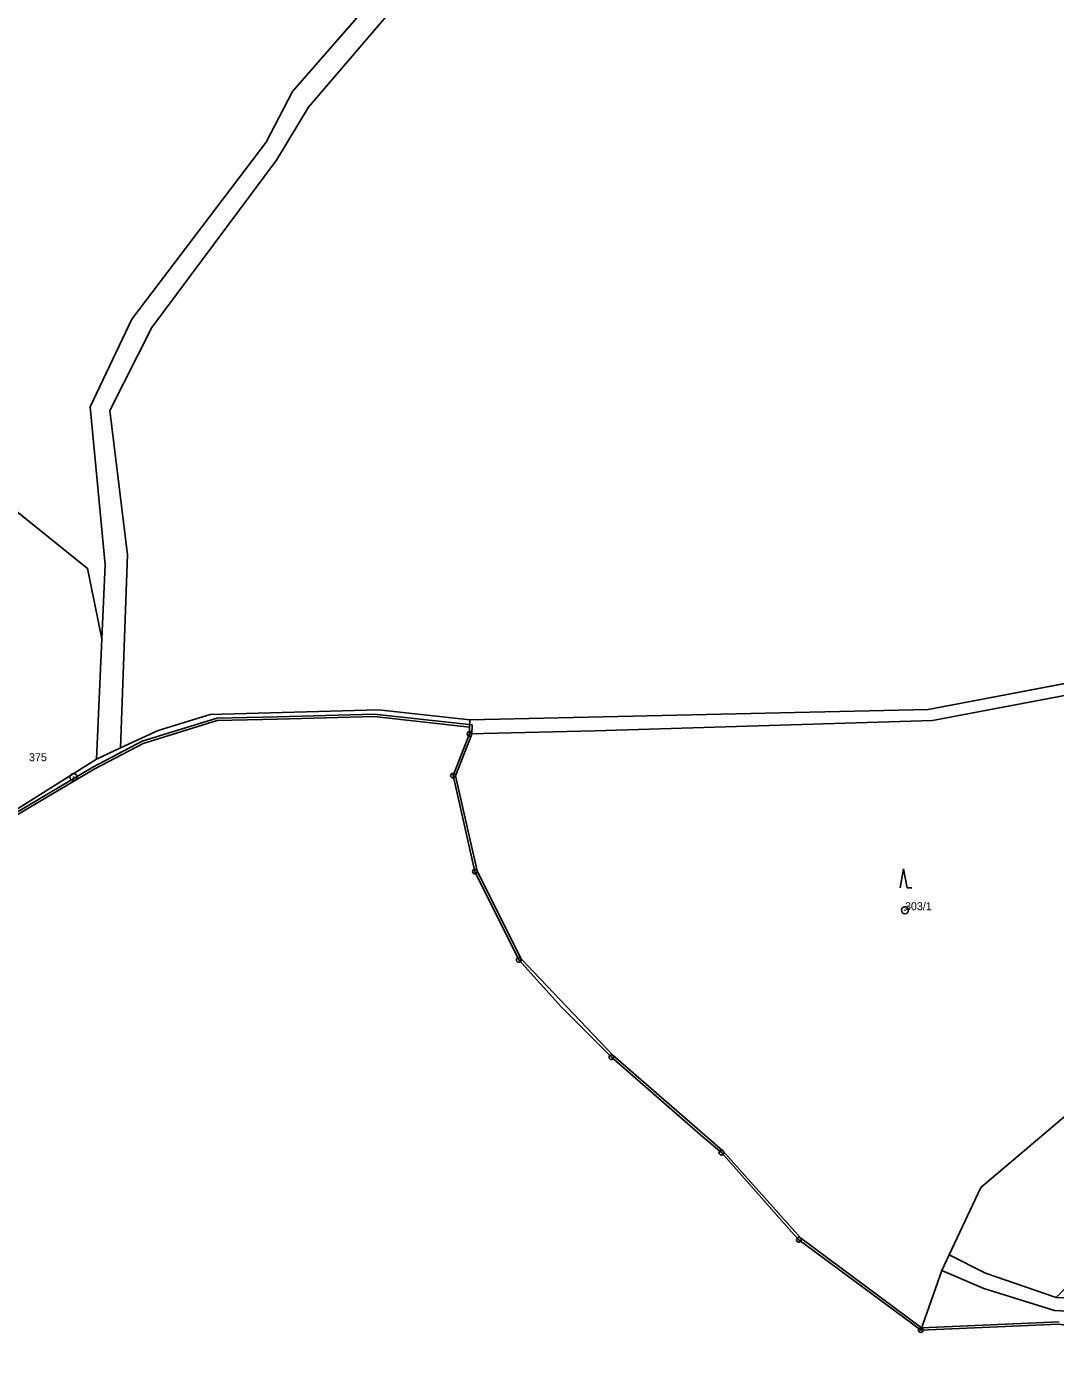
# Model space of a CAD drawing. Extents: x -652854 to -650068, y -1097661 to -1095417.
# Drawn here: x -651919.6 to -651701, y -1097612.7 to -1097329.6 of the extents above; entities that cross this region are included whole.
import ezdxf

# ---------------------------------------------------------------- set-up
doc = ezdxf.new("R2010")
doc.units = 0
for name, color, linetype in [('Definiční body parcel', 7, 'Continuous'), ('Geodetické body', 7, 'Continuous'), ('Hranice obcí', 7, 'Continuous'), ('Hranice parcel', 7, 'Continuous'), ('Obvody jako plochy', 7, 'Continuous'), ('Ostatní hranice', 7, 'Continuous'), ('Parcelní čísla', 7, 'Continuous'), ('Prvky pro prodl_ par_ č_', 7, 'Continuous'), ('Značky kultur', 7, 'Continuous')]:
    doc.layers.add(name, color=color, linetype=linetype)

msp = doc.modelspace()

# ---------------------------------------------------------------- linework, layer by layer
at = {"layer": 'Definiční body parcel'}
for centre, radius in [((-651909.62, -1097489), 0.75), ((-651909.62, -1097489), 0.0327), ((-651732.94, -1097517.28), 0.75), ((-651732.94, -1097517.28), 0.0327)]:
    msp.add_circle(centre, radius, dxfattribs=at)
at = {"layer": 'Geodetické body'}
for centre, radius in [((-651825.47, -1097479.81), 0.5), ((-651825.47, -1097479.81), 0.001), ((-651828.98, -1097488.69), 0.5), ((-651828.98, -1097488.69), 0.001), ((-651824.33, -1097509.08), 0.5), ((-651824.33, -1097509.08), 0.001), ((-651815, -1097527.82), 0.5), ((-651815, -1097527.82), 0.001), ((-651795.32, -1097548.52), 0.5), ((-651795.32, -1097548.52), 0.001), ((-651771.96, -1097568.78), 0.5), ((-651771.96, -1097568.78), 0.001), ((-651755.48, -1097587.3), 0.5), ((-651755.48, -1097587.3), 0.001), ((-651729.58, -1097606.47), 0.5), ((-651729.58, -1097606.47), 0.5), ((-651729.58, -1097606.47), 0.001), ((-651729.58, -1097606.47), 0.001)]:
    msp.add_circle(centre, radius, dxfattribs=at)
at = {"layer": 'Hranice obcí'}
for p, q in [((-651845.76, -1097476.13), (-651866.27, -1097476.71)), ((-651825.44, -1097478.37), (-651845.76, -1097476.13)), ((-651879.09, -1097476.97), (-651894.83, -1097481.83)), ((-651866.27, -1097476.71), (-651879.09, -1097476.97)), ((-651825.47, -1097479.81), (-651825.44, -1097478.37)), ((-651894.83, -1097481.83), (-651905.26, -1097487.34)), ((-651828.98, -1097488.69), (-651825.47, -1097479.81)), ((-651905.26, -1097487.34), (-651927.04, -1097500.22)), ((-651824.33, -1097509.08), (-651828.98, -1097488.69)), ((-651815, -1097527.82), (-651824.33, -1097509.08)), ((-651805.95, -1097537.85), (-651815, -1097527.82)), ((-651795.32, -1097548.52), (-651805.95, -1097537.85)), ((-651795.32, -1097548.52), (-651775.8, -1097565.46)), ((-651775.8, -1097565.46), (-651771.96, -1097568.78)), ((-651771.96, -1097568.78), (-651756.45, -1097586.21)), ((-651756.45, -1097586.21), (-651755.48, -1097587.3)), ((-651755.48, -1097587.3), (-651731.57, -1097605)), ((-651731.57, -1097605), (-651729.58, -1097606.47)), ((-651700.22, -1097605.21), (-651729.58, -1097606.47))]:
    msp.add_line(p, q, dxfattribs=at)
at = {"layer": 'Hranice parcel'}
for p, q in [((-651843.88, -1097321.35), (-651863.05, -1097343.32)), ((-651840.2, -1097323.89), (-651859.69, -1097346.64)), ((-651863.05, -1097343.32), (-651868.68, -1097354.1)), ((-651859.69, -1097346.64), (-651866.47, -1097357.95)), ((-651868.68, -1097354.1), (-651897.24, -1097391.74)), ((-651866.47, -1097357.95), (-651892.98, -1097393.51)), ((-651897.24, -1097391.74), (-651906.06, -1097410.33)), ((-651892.98, -1097393.51), (-651901.87, -1097411.14)), ((-651906.06, -1097410.33), (-651902.87, -1097443.89)), ((-651901.87, -1097411.14), (-651898.12, -1097441.79)), ((-651906.62, -1097444.67), (-651926.46, -1097428.73)), ((-651898.12, -1097441.79), (-651899.65, -1097482.78)), ((-651903.58, -1097459.6), (-651906.62, -1097444.67)), ((-651902.87, -1097443.89), (-651903.58, -1097459.6)), ((-651596.98, -1097449.79), (-651728.02, -1097474.61)), ((-651727.11, -1097476.95), (-651599.33, -1097452.83)), ((-651903.58, -1097459.6), (-651904.74, -1097485.18)), ((-651880.59, -1097475.68), (-651891.62, -1097479.11)), ((-651844.81, -1097474.74), (-651880.59, -1097475.68)), ((-651825.38, -1097476.82), (-651844.81, -1097474.74)), ((-651728.02, -1097474.61), (-651825.38, -1097476.82)), ((-651891.62, -1097479.11), (-651899.65, -1097482.78)), ((-651825.47, -1097479.81), (-651798.82, -1097479.19)), ((-651825.38, -1097476.82), (-651825.44, -1097478.37)), ((-651798.82, -1097479.19), (-651727.11, -1097476.95)), ((-651899.65, -1097482.78), (-651904.74, -1097485.18)), ((-651904.74, -1097485.18), (-651928.47, -1097500.08)), ((-651686.19, -1097550.23), (-651716.83, -1097576.15)), ((-651716.83, -1097576.15), (-651723.58, -1097590.51)), ((-651723.58, -1097590.51), (-651725.08, -1097593.81)), ((-651723.58, -1097590.51), (-651715.83, -1097594.35)), ((-651725.08, -1097593.81), (-651729.58, -1097606.47)), ((-651725.08, -1097593.81), (-651716.15, -1097597.61)), ((-651715.83, -1097594.35), (-651700.83, -1097599.54)), ((-651716.15, -1097597.61), (-651701.14, -1097602.34)), ((-651701.14, -1097602.34), (-651644.13, -1097605.5))]:
    msp.add_line(p, q, dxfattribs=at)
at = {"layer": 'Obvody jako plochy'}
for points in [[(-651926.46, -1097428.73), (-651906.62, -1097444.67), (-651903.58, -1097459.6), (-651902.87, -1097443.89), (-651906.06, -1097410.33), (-651897.24, -1097391.74), (-651868.68, -1097354.1), (-651863.05, -1097343.32), (-651843.88, -1097321.35), (-651835.59, -1097289.34), (-651799.03, -1097243.39), (-651765.96, -1097199.26), (-651747.99, -1097187.53), (-651693.61, -1097158.93), (-651646.28, -1097138.78), (-651606.05, -1097138.21), (-651573.39, -1097130.09), (-651561.36, -1097123.06), (-651550.73, -1097110.1), (-651546.83, -1097095.59), (-651550.89, -1097076.68), (-651563.08, -1097040.57)], [(-651694.17, -1097165.26), (-651745.78, -1097190.99), (-651763.09, -1097202.67), (-651785, -1097232.05), (-651832.56, -1097292.73), (-651840.2, -1097323.89), (-651859.69, -1097346.64), (-651866.47, -1097357.95), (-651892.98, -1097393.51), (-651901.87, -1097411.14), (-651898.12, -1097441.79), (-651899.65, -1097482.78), (-651891.62, -1097479.11), (-651880.59, -1097475.68), (-651844.81, -1097474.74), (-651825.38, -1097476.82), (-651728.02, -1097474.61), (-651596.98, -1097449.79)], [(-651843.88, -1097321.35), (-651863.05, -1097343.32), (-651868.68, -1097354.1), (-651897.24, -1097391.74), (-651906.06, -1097410.33), (-651902.87, -1097443.89), (-651903.58, -1097459.6), (-651904.74, -1097485.18), (-651899.65, -1097482.78), (-651898.12, -1097441.79), (-651901.87, -1097411.14), (-651892.98, -1097393.51), (-651866.47, -1097357.95), (-651859.69, -1097346.64), (-651840.2, -1097323.89)], [(-651599.33, -1097452.83), (-651727.11, -1097476.95), (-651798.82, -1097479.19), (-651825.47, -1097479.81), (-651828.98, -1097488.69), (-651824.33, -1097509.08), (-651815, -1097527.82), (-651805.95, -1097537.85), (-651795.32, -1097548.52), (-651775.8, -1097565.46), (-651771.96, -1097568.78), (-651756.45, -1097586.21), (-651755.48, -1097587.3), (-651731.57, -1097605), (-651729.58, -1097606.47), (-651725.08, -1097593.81), (-651723.58, -1097590.51), (-651716.83, -1097576.15), (-651686.19, -1097550.23)]]:
    msp.add_lwpolyline(points, dxfattribs=at)
for points in [[(-651906.62, -1097444.67), (-651926.46, -1097428.73), (-651941.31, -1097422.01), (-651952.88, -1097410.23), (-651963.67, -1097405.07), (-651985.25, -1097400.69), (-652016.53, -1097380.82), (-652032.05, -1097377.13), (-652034.08, -1097388.46), (-652004.99, -1097425.22), (-651959.09, -1097482.19), (-651936.64, -1097509.95), (-651928.47, -1097500.08), (-651904.74, -1097485.18), (-651903.58, -1097459.6)], [(-651355.9, -1097395.18), (-651352.74, -1097391.59), (-651436.3, -1097432.32), (-651530.5, -1097442.54), (-651596.98, -1097449.79), (-651728.02, -1097474.61), (-651825.38, -1097476.82), (-651825.44, -1097478.37), (-651825.47, -1097479.81), (-651798.82, -1097479.19), (-651727.11, -1097476.95), (-651599.33, -1097452.83), (-651593.84, -1097451.76), (-651467.92, -1097437.92), (-651434.39, -1097434.71)], [(-651825.38, -1097476.82), (-651844.81, -1097474.74), (-651880.59, -1097475.68), (-651891.62, -1097479.11), (-651899.65, -1097482.78), (-651904.74, -1097485.18), (-651928.47, -1097500.08), (-651936.64, -1097509.95), (-651954, -1097530.05), (-651964.22, -1097538.47), (-651966.36, -1097540.92), (-651967.51, -1097542.9), (-651973.77, -1097554.49), (-651973.16, -1097555.12), (-651964.84, -1097541.04), (-651955.29, -1097533.32), (-651941.43, -1097519.36), (-651927.04, -1097500.22), (-651905.26, -1097487.34), (-651894.83, -1097481.83), (-651879.09, -1097476.97), (-651866.27, -1097476.71), (-651845.76, -1097476.13), (-651825.44, -1097478.37)], [(-651716.83, -1097576.15), (-651723.58, -1097590.51), (-651715.83, -1097594.35), (-651700.83, -1097599.54), (-651675.12, -1097574.18), (-651654.22, -1097558.94), (-651635.4, -1097533.46), (-651652.64, -1097522.63), (-651686.19, -1097550.23)], [(-651725.08, -1097593.81), (-651716.15, -1097597.61), (-651701.14, -1097602.34), (-651644.13, -1097605.5), (-651574.8, -1097612.59), (-651562.37, -1097608.51), (-651541.07, -1097597.57), (-651569.57, -1097607.22), (-651649.26, -1097601.77), (-651700.83, -1097599.54), (-651715.83, -1097594.35), (-651723.58, -1097590.51)], [(-651725.08, -1097593.81), (-651729.58, -1097606.47), (-651700.22, -1097605.21), (-651668.43, -1097609.93), (-651647.03, -1097610.47), (-651629.7, -1097610.9), (-651623.13, -1097611.06), (-651610.03, -1097612.05), (-651594.11, -1097612.69), (-651579.78, -1097612.61), (-651574.8, -1097612.59), (-651644.13, -1097605.5), (-651701.14, -1097602.34), (-651716.15, -1097597.61)]]:
    msp.add_lwpolyline(points, close=True, dxfattribs=at)
at = {"layer": 'Ostatní hranice'}
for p, q in [((-651895, -1097481.35), (-651879.14, -1097476.46)), ((-651879.14, -1097476.46), (-651866.26, -1097476.2)), ((-651866.26, -1097476.2), (-651845.72, -1097475.62)), ((-651824.91, -1097477.91), (-651845.72, -1097475.62)), ((-651824.96, -1097479.86), (-651824.91, -1097477.91)), ((-651905.49, -1097486.88), (-651895, -1097481.35)), ((-651828.47, -1097488.71), (-651824.96, -1097479.86)), ((-651927.36, -1097499.83), (-651905.49, -1097486.88)), ((-651823.85, -1097508.92), (-651828.47, -1097488.71)), ((-651814.59, -1097527.51), (-651823.85, -1097508.92)), ((-651794.97, -1097548.15), (-651814.59, -1097527.51)), ((-651775.46, -1097565.09), (-651794.97, -1097548.15)), ((-651771.61, -1097568.42), (-651775.46, -1097565.09)), ((-651755.17, -1097586.9), (-651771.61, -1097568.42)), ((-651729.41, -1097605.99), (-651755.17, -1097586.9)), ((-651700.16, -1097604.7), (-651729.41, -1097605.99))]:
    msp.add_line(p, q, dxfattribs=at)
at = {"layer": 'Značky kultur'}
for p, q in [((-651733.222, -1097508.519), (-651733.955, -1097512.519)), ((-651733.222, -1097508.519), (-651732.489, -1097512.519)), ((-651732.489, -1097512.519), (-651731.489, -1097512.519))]:
    msp.add_line(p, q, dxfattribs=at)

# ---------------------------------------------------------------- texts
at = {"layer": 'Parcelní čísla'}
for s, height, p in [('375', 0.1, (-651909.62, -1097489)), ('303/1', 1.7, (-651732.94, -1097517.28))]:
    msp.add_text(s, height=height, dxfattribs=at).set_placement(p)
at = {"layer": 'Prvky pro prodl_ par_ č_'}
msp.add_text('375', height=1.7, dxfattribs=at).set_placement((-651919.08, -1097485.62))

doc.saveas('drawing.dxf')
